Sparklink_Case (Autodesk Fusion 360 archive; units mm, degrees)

design "Sparklink Case" references "Halbrundschraube JIS B 1111 - M3x6 Stahl 4.6 Einfach", "SparkLink"
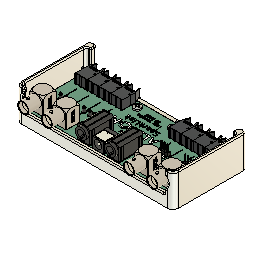
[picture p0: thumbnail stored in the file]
sketch "Skizze1" plane through (0, 0, 0) normal (0, 0, 1) x axis (1, 0, 0)
  line L1 (128, 0) -> (2, 0)
  line L2 (130, 53) -> (130, 2)
  line L3 (2, 55) -> (128, 55)
  line L4 (0, 2) -> (0, 53)
  line L5 (-0.1, 2) -> (-0.1, 53)
  line L6 (128, -0.1) -> (2, -0.1)
  line L7 (130.1, 53) -> (130.1, 2)
  line L8 (2, 55.1) -> (128, 55.1)
  line L9 (-3.1, 2) -> (-3.1, 53)
  line L10 (128, -3.1) -> (2, -3.1)
  line L11 (133.1, 53) -> (133.1, 2)
  line L12 (2, 58.1) -> (128, 58.1)
  arc A1 centre (2, 53) radius 2 clockwise from (0, 53) to (2, 55)
  arc A2 centre (2, 2) radius 2 clockwise from (2, 0) to (0, 2)
  arc A3 centre (128, 53) radius 2 clockwise from (128, 55) to (130, 53)
  arc A4 centre (128, 2) radius 2 clockwise from (130, 2) to (128, 0)
  arc A5 centre (2, 2) radius 2.1 clockwise from (2, -0.1) to (-0.1, 2)
  arc A6 centre (128, 2) radius 2.1 clockwise from (130.1, 2) to (128, -0.1)
  arc A7 centre (128, 53) radius 2.1 clockwise from (128, 55.1) to (130.1, 53)
  arc A8 centre (2, 53) radius 2.1 clockwise from (-0.1, 53) to (2, 55.1)
  arc A9 centre (2, 2) radius 5.1 clockwise from (2, -3.1) to (-3.1, 2)
  arc A10 centre (128, 2) radius 5.1 clockwise from (133.1, 2) to (128, -3.1)
  arc A11 centre (128, 53) radius 5.1 clockwise from (128, 58.1) to (133.1, 53)
  arc A12 centre (2, 53) radius 5.1 clockwise from (-3.1, 53) to (2, 58.1)
  point P1 (0, 0)
  point P2 (0, 0)
  point P4 (0, 55)
  point P3 (130, 0)
  horizontal L1
  vertical L2
  horizontal L3
  vertical L4
  coincident P1 P2
  coincident P4 L3
  coincident P4 L4
  tangent L3 A1
  tangent L4 A1
  coincident P2 L1
  coincident P2 L4
  tangent L1 A2
  tangent L4 A2
  equal A1 A2
  tangent L2 A3
  tangent L3 A3
  equal A1 A3
  coincident P3 L1
  coincident P3 L2
  tangent L1 A4
  tangent L2 A4
  equal A1 A4
  dimension "d1" distance P2 P3 = 130
  dimension "d2" distance P2 P4 = 55
  dimension "d3" radius A1 = 2
  dimension "d4" = 0.1
  dimension "d5" = 3.1
extrude "Extrusion1" new body sketch "Skizze1" profile of A8 L5 A7 A5 L7 L8 A6 L6 A12 L10 A9 A11 L11 L12 A10 L9 against normal blind 10
sketch "Skizze2" plane through (0, 0, -10) normal (0, 0, -1) x axis (1, 0, 0)
  line L1 (-0.1, -2) -> (-0.1, -53)
  line L2 (128, 0.1) -> (2, 0.1)
  line L3 (130.1, -53) -> (130.1, -2)
  line L4 (2, -55.1) -> (128, -55.1)
  line L5 (128, -58.1) -> (2, -58.1)
  line L6 (133.1, -2) -> (133.1, -53)
  line L7 (2, 3.1) -> (128, 3.1)
  line L8 (-3.1, -53) -> (-3.1, -2)
  arc A1 centre (2, -53) radius 2.1 clockwise from (2, -55.1) to (-0.1, -53)
  arc A2 centre (2, -2) radius 2.1 clockwise from (-0.1, -2) to (2, 0.1)
  arc A3 centre (128, -2) radius 2.1 clockwise from (128, 0.1) to (130.1, -2)
  arc A4 centre (128, -53) radius 2.1 clockwise from (130.1, -53) to (128, -55.1)
  arc A5 centre (2, -53) radius 5.1 clockwise from (2, -58.1) to (-3.1, -53)
  arc A6 centre (128, -53) radius 5.1 clockwise from (133.1, -53) to (128, -58.1)
  arc A7 centre (128, -2) radius 5.1 clockwise from (128, 3.1) to (133.1, -2)
  arc A8 centre (2, -2) radius 5.1 clockwise from (-3.1, -2) to (2, 3.1)
extrude "Extrusion2" add sketch "Skizze2" profile of A1 L1 A2 L2 A3 L3 A4 L4 against normal blind 3
extrude "Extrusion3" add of existing geometry blind 18
sketch "Skizze3" plane through (0, 0, -7) normal (0, 0, 1) x axis (-1, 0, 0)
  line L1 (-130.1, -53) -> (-130.1, -2)
  line L2 (-2, -55.1) -> (-128, -55.1)
  line L3 (0.1, -2) -> (0.1, -53)
  line L4 (-128, 0.1) -> (-2, 0.1)
  line L5 (-65, -55.1) -> (-65, 0.1)
  line L6 (-19.28, -8.18) -> (-110.72, -8.18)
  line L7 (-49.76, -49.455) -> (-80.24, -49.455)
  arc A1 centre (-128, -2) radius 2.1 clockwise from (-130.1, -2) to (-128, 0.1)
  arc A2 centre (-128, -53) radius 2.1 clockwise from (-128, -55.1) to (-130.1, -53)
  arc A3 centre (-2, -53) radius 2.1 clockwise from (0.1, -53) to (-2, -55.1)
  arc A4 centre (-2, -2) radius 2.1 clockwise from (-2, 0.1) to (0.1, -2)
  circle C1 centre (-110.72, -8.18) radius 1.45
  circle C2 centre (-19.28, -8.18) radius 1.45
  circle C3 centre (-80.24, -49.455) radius 1.45
  circle C4 centre (-49.76, -49.455) radius 1.45
  circle C5 centre (-110.72, -8.18) radius 4
  circle C6 centre (-19.28, -8.18) radius 4
  circle C7 centre (-49.76, -49.455) radius 4
  circle C8 centre (-80.24, -49.455) radius 4
  point P14 (-110.72, -8.18)
  point P15 (-19.28, -8.18)
  point P16 (-80.24, -49.455)
  point P17 (-49.76, -49.455)
  point P18 (-65, 0.1)
  point P19 (-65, -55.1)
  point P20 (-110.72, -8.18)
  point P21 (-19.28, -8.18)
  point P22 (-80.24, -49.455)
  point P23 (-49.76, -49.455)
  point P26 (-49.76, -49.455)
  horizontal P14 P15
  horizontal P16 P17
  midpoint L4 P18
  midpoint L2 P19
  coincident P14 P20
  coincident P15 P21
  coincident P16 P22
  coincident P17 P23
  concentric C1 C5
  concentric C2 C6
  coincident P23 P26
  concentric C3 C8
  dimension "d13" diameter C1 = 2.9
  dimension "d14" diameter C2 = 2.9
  dimension "d15" distance P14 P15 = 91.44
  dimension "d16" diameter C3 = 2.9
  dimension "d17" diameter C4 = 2.9
  dimension "d18" distance P16 P17 = 30.48
  dimension "d19" distance P14 P16 = 41.275
  dimension "d20" distance P16 L5 = 15.24 (= "d18 / 2")
  dimension "d21" distance P14 L5 = 45.72 (= "d15 / 2")
  dimension "d22" distance L4 L6 = 8.28
  dimension "d24" diameter C5 = 8
  dimension "d25" diameter C6 = 8
  dimension "d26" diameter C7 = 8
  dimension "d27" diameter C8 = 8
extrude "Extrusion4" add sketch "Skizze3" profile of C1 C2 C3 C4 C5 C6 C7 C8 along normal blind 5
component_insert "Komponente einfügen" sketch "Skizze3"
as_built_joint "Bestand"
joint "Zusammenfügen" alignAngle 180 alignOffsetX 0 alignOffsetY 0 alignOffsetZ 0
sketch "Skizze4" plane through (0, 58.1, 0) normal (0, 1, 0) x axis (-1, 0, 0)
  line L1 (-2, 18) -> (-2, -10)
  line L2 (-128, 18) -> (-2, 18)
  line L3 (-128, -10) -> (-128, 18)
  line L4 (-127.5, 18) -> (-128, 18)
  line L5 (-126.5, 0.56) -> (-126.5, 17)
  line L6 (-4.5, -0.44) -> (-125.5, -0.44)
  line L7 (-3.5, 17) -> (-3.5, 0.56)
  line L8 (-2.5, 18) -> (-2, 18)
  line L9 (-65, -18.88) -> (-65, 18)
  line L10 (-2, -10) -> (-128, -10)
  arc A1 centre (-2.5, 17) radius 1 clockwise from (-3.5, 17) to (-2.5, 18)
  arc A2 centre (-4.5, 0.56) radius 1 clockwise from (-3.5, 0.56) to (-4.5, -0.44)
  arc A3 centre (-125.5, 0.56) radius 1 clockwise from (-125.5, -0.44) to (-126.5, 0.56)
  arc A4 centre (-127.5, 17) radius 1 clockwise from (-127.5, 18) to (-126.5, 17)
  point P5 (-128, 18)
  point P6 (-128, 18)
  point P9 (-3.5, 18)
  point P4 (-2, 18)
  point P10 (-2, 18)
  point P8 (-3.5, -0.44)
  point P7 (-126.5, -0.44)
  point P23 (-65, 18)
  coincident P5 P6
  perpendicular L4 L5
  perpendicular L1 L6
  coincident L2 P9
  perpendicular L2 L7
  coincident P4 P10
  coincident P9 L7
  coincident P9 L8
  tangent L7 A1
  tangent L8 A1
  coincident P8 L6
  coincident P8 L7
  tangent L6 A2
  tangent L7 A2
  equal A1 A2
  coincident P7 L5
  coincident P7 L6
  tangent L5 A3
  tangent L6 A3
  equal A1 A3
  tangent L4 A4
  tangent L5 A4
  parallel L3 L5
  midpoint L2 P23
  midpoint L6 L9
  dimension "d34" distance P7 P8 = 123
  dimension "d35" distance P8 P9 = 18.44 (= "18 mm + 0.44 mm")
  dimension "d36" radius A1 = 1
  dimension "d37" radius A4 = 1
extrude "Extrusion5" cut sketch "Skizze4" profile of L2 L3 L5 L6 L7 A1 A2 A3 A4 against normal blind 5
sketch "Skizze5" plane through (0, -3.1, 0) normal (0, -1, 0) x axis (1, 0, 0)
  line L1 (128, 18) -> (128, -10)
  line L2 (2, 18) -> (128, 18)
  line L3 (2, -10) -> (2, 18)
  line L4 (2.5, 18) -> (2, 18)
  line L5 (4, 1.06) -> (4, 16.5)
  line L6 (124.5, -0.44) -> (5.5, -0.44)
  line L7 (126, 16.5) -> (126, 1.06)
  line L8 (127.5, 18) -> (128, 18)
  line L9 (128, -10) -> (2, -10)
  arc A1 centre (124.5, 1.06) radius 1.5 clockwise from (126, 1.06) to (124.5, -0.44)
  arc A2 centre (5.5, 1.06) radius 1.5 clockwise from (5.5, -0.44) to (4, 1.06)
  arc A3 centre (2.5, 16.5) radius 1.5 clockwise from (2.5, 18) to (4, 16.5)
  arc A4 centre (127.5, 16.5) radius 1.5 clockwise from (126, 16.5) to (127.5, 18)
  point P5 (2, 18)
  point P6 (2, 18)
  point P8 (126, -0.44)
  point P7 (4, -0.44)
  point P4 (128, 18)
  point P18 (128, 18)
  coincident P5 P6
  perpendicular L4 L5
  perpendicular L1 L6
  perpendicular L2 L7
  vertical L5
  coincident P8 L6
  coincident P8 L7
  tangent L6 A1
  tangent L7 A1
  coincident P7 L5
  coincident P7 L6
  tangent L5 A2
  tangent L6 A2
  tangent L4 A3
  tangent L5 A3
  equal A2 A3
  coincident P4 P18
  perpendicular L1 L8
  tangent L8 A4
  tangent L7 A4
  equal A1 A4
  equal L4 L8
  dimension "d40" distance L2 L6 = 18.44
  dimension "d41" distance P7 P8 = 122
  dimension "d45" radius A4 = 1.5
  dimension "d46" radius A3 = 1.5
extrude "Extrusion6" cut sketch "Skizze5" profile of L2 L5 L6 L7 A1 A2 A3 against normal blind 3
step "Schraube2"
step "Schraube4"
step "Schraube5"
step "Schraube6"
sketch "Skizze6" plane through (0, -3.1, 0) normal (0, -1, 0) x axis (1, 0, 0)
  line L1 (2, 18) -> (2.5, 18)
  line L2 (2, -10) -> (2, 18)
  line L3 (128, -10) -> (2, -10)
  line L4 (128, 18) -> (128, -10)
  line L5 (127.5, 18) -> (128, 18)
  line L6 (126, 1.06) -> (126, 16.5)
  line L7 (5.5, -0.44) -> (124.5, -0.44)
  line L8 (4, 16.5) -> (4, 1.06)
  arc A1 centre (2.5, 16.5) radius 1.5 clockwise from (2.5, 18) to (4, 16.5)
  arc A2 centre (127.5, 16.5) radius 1.5 clockwise from (126, 16.5) to (127.5, 18)
  arc A3 centre (124.5, 1.06) radius 1.5 clockwise from (126, 1.06) to (124.5, -0.44)
  arc A4 centre (5.5, 1.06) radius 1.5 clockwise from (5.5, -0.44) to (4, 1.06)
  circle C1 centre (9.12, 8.59) radius 7.5
  circle C2 centre (120.88, 8.59) radius 7.5
  point P18 (9.12, 8.59)
  point P19 (120.88, 8.59)
  dimension "d51" diameter C1 = 15
  dimension "d52" diameter C2 = 15
  dimension "d53" distance L8 P18 = 5.12
  dimension "d54" distance L7 P18 = 9.03
  dimension "d55" distance L6 P19 = 5.12 (= "d53")
  dimension "d56" distance L7 P19 = 9.03 (= "d54")
extrude "Extrusion7" cut sketch "Skizze6" profile of L2 L4 L6 L8 C1 C2 against normal blind 5
fillet "Abrundung1" radius 2
sketch "Skizze7" plane through (0, 0, 18) normal (0, 0, 1) x axis (-1, 0, 0)
  line L1 (-127.5, 3.1) -> (-127.5, 0.1)
  line L2 (-128, 3.1) -> (-127.5, 3.1)
  line L3 (-133.1, -53) -> (-133.1, -2)
  line L4 (-127.5, -58.1) -> (-128, -58.1)
  line L5 (-127.5, -55.1) -> (-127.5, -58.1)
  line L6 (-128, -55.1) -> (-127.5, -55.1)
  line L7 (-130.1, -2) -> (-130.1, -53)
  line L8 (-127.5, 0.1) -> (-128, 0.1)
  line L9 (-133.1, -56) -> (-133.1, -53)
  line L10 (-126.5, -61.0996) -> (-126.5, -58.0996)
  line L11 (-133.1, -61.0996) -> (-126.5, -61.0996)
  line L12 (-133.1, -56) -> (-133.1, -61.0996)
  line L13 (-126.5, -58.0996) -> (-127.5, -58.1)
  arc A1 centre (-128, -2) radius 5.1 clockwise from (-133.1, -2) to (-128, 3.1)
  arc A2 centre (-128, -53) radius 5.1 clockwise from (-128, -58.1) to (-133.1, -53)
  arc A3 centre (-128, -53) radius 2.1 clockwise from (-128, -55.1) to (-130.1, -53)
  arc A4 centre (-128, -2) radius 2.1 clockwise from (-130.1, -2) to (-128, 0.1)
  point P7 (-133.1, -53)
  point P16 (-133.1, -53)
  point P10 (-127.5, -58.1)
  point P21 (-127.5, -58.1)
  point P18 (-126.5, -58.0996)
  point P19 (-126.5, -61.0996)
  coincident P7 P16
  tangent A2 L9
  parallel L9 L10
  perpendicular L10 L11
  vertical L12
  coincident P10 P21
  dimension "d61" distance P18 P19 = 3
extrude "Extrusion8" add sketch "Skizze7" profile of A2 L4 L9 L10 L11 L12 L13 against normal blind 28
fillet "Abrundung4" radius 2.9
fillet "Abrundung5" radius 2.9
sketch "Skizze8" plane through (0, 0, 18) normal (0, 0, 1) x axis (-1, 0, 0)
  line L1 (-2.5, 0.1) -> (-2.5, 3.1)
  line L2 (-2, 0.1) -> (-2.5, 0.1)
  line L3 (0.1, -53) -> (0.1, -2)
  line L4 (-2.5, -55.1) -> (-2, -55.1)
  line L5 (-2.5, -58.1) -> (-2.5, -55.1)
  line L6 (-2, -58.1) -> (-2.5, -58.1)
  line L7 (3.1, -2) -> (3.1, -53)
  line L8 (-2.5, 3.1) -> (-2, 3.1)
  line L9 (3.1, -56) -> (3.1, -53)
  line L10 (-3.5, -61.1) -> (-3.5, -58.1)
  line L11 (3.1, -61.1) -> (-3.5, -61.1)
  line L12 (3.1, -56) -> (3.1, -61.1)
  line L13 (-2, -58.1) -> (-3.5, -58.1)
  arc A1 centre (-2, -2) radius 2.1 clockwise from (-2, 0.1) to (0.1, -2)
  arc A2 centre (-2, -53) radius 2.1 clockwise from (0.1, -53) to (-2, -55.1)
  arc A3 centre (-2, -53) radius 5.1 clockwise from (3.1, -53) to (-2, -58.1)
  arc A4 centre (-2, -2) radius 5.1 clockwise from (-2, 3.1) to (3.1, -2)
  point P13 (3.1, -53)
  point P16 (3.1, -53)
  point P12 (-2, -58.1)
  point P21 (-2, -58.1)
  point P18 (-3.5, -58.1)
  point P19 (-3.5, -61.1)
  coincident P13 P16
  tangent A3 L9
  vertical L10
  perpendicular L10 L11
  vertical L12
  coincident P12 P21
  tangent A3 L13
  dimension "d72" distance P18 P19 = 3
extrude "Extrusion9" add sketch "Skizze8" profile of L6 A3 L9 L10 L11 L12 L13 against normal blind 28
fillet "Abrundung6" radius 2.9
fillet "Abrundung7" radius 1
fillet "Abrundung9" radius 1
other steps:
joint_origin "Gelenkursprung"

design "Halbrundschraube JIS B 1111 - M3x6 Stahl 4.6 Einfach"
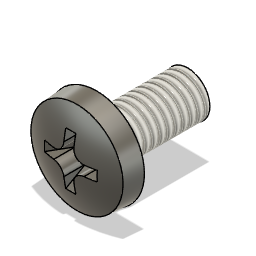
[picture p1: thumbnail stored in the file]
description: Halbrundschraube JIS B 1111 - M3x6
part number: BHS JIS B 1111 - M3x6 Stahl 4.6 Einfach
parameter "adsk_nomdia" = 3
parameter "adsk_nomlen" = 6
parameter "adsk_headdia" = 6.3
parameter "adsk_baseh" = 1.3
parameter "adsk_phildia" = 3.7
parameter "adsk_midfillet" = 0.1
parameter "adsk_thrlen" = 5.06
parameter "adsk_phildepth" = 1.53
parameter "adsk_thrrun" = 0.75
parameter "adsk_thrang" = 15
parameter "adsk_headang" = 5
parameter "adsk_ovalh" = 0.6
parameter "adsk_philwidth" = 0.662
sketch "Sketch1" plane through (0, 0, 0) normal (0, 1, 0) x axis (1, 0, 0)
  line L1 (0, 6) -> (0, -1.9)
  line L2 (-3.0363, -1.3) -> (-3.15, 0)
  line L3 (-1.299, 0) -> (-3.15, 0)
  line L4 (-1.5, 6) -> (0, 6)
  line L5 (-1.5, 0.94) -> (-1.5, 6)
  line L6 (-1.299, 0.19) -> (-1.5, 0.94)
  line L7 (-1.299, 0) -> (-1.299, 0.19)
  arc A1 centre (0, 6.0824) radius 7.9824 clockwise from (0, -1.9) to (-3.0363, -1.3)
  point P1 (0, 0)
  point P8 (0, -1.9)
  point P7 (0, 6.0824)
  point P2 (0, -1.9)
  point P6 (-1.299, 0)
  point P12 (-1.299, 0)
  point P10 (-1.5, 0.94)
  point P11 (-1.299, 0.19)
  point P5 (-3.0363, -1.3)
  vertical L1
  coincident P1 L1
  horizontal L3
  coincident P1 L3
  coincident L1 P8
  coincident L1 P7
  coincident P2 P8
  perpendicular L1 L4
  perpendicular L4 L5
  vertical L7
  coincident P6 P12
  dimension "d13" angle L1 L2 = 5 (= "adsk_headang")
  dimension "d14" = 6.3 (= "adsk_headdia")
  dimension "d18" = 3 (= "adsk_nomdia")
  dimension "d23" angle L5 L6 = 15 (= "adsk_thrang")
  dimension "d53" distance P2 L3 = 1.9 (= "adsk_baseh + adsk_ovalh")
  dimension "d55" distance L4 P10 = 5.06 (= "adsk_thrlen")
  dimension "d56" distance L3 L4 = 6 (= "adsk_nomlen")
  dimension "d57" distance L4 P11 = 5.81 (= "adsk_thrlen + adsk_thrrun")
  dimension "d60" distance P5 L3 = 1.3 (= "adsk_baseh")
revolve "Revolve1" sketch "Sketch1" AlongAngle 360
fillet "Fillet2" radius 0.1 (= "adsk_midfillet")
work_plane "WorkPlane1" AlongDistance 1.9 (= "adsk_baseh + adsk_ovalh")
sketch "Sketch2" plane through (0, 0, 1.9) normal (0, 0, 1) x axis (1, 0, 0)
  line L1 (1.85, 0) -> (-1.85, 0)
  line L2 (0, 1.85) -> (0, -1.85)
  line L3 (0.331, 1.85) -> (-0.331, 1.85)
  line L4 (0.331, 0.331) -> (0.331, 1.85)
  line L5 (1.85, 0.331) -> (0.331, 0.331)
  line L6 (1.85, -0.331) -> (1.85, 0.331)
  line L7 (0.331, -0.331) -> (1.85, -0.331)
  line L8 (0.331, -1.85) -> (0.331, -0.331)
  line L9 (-0.331, -1.85) -> (0.331, -1.85)
  line L10 (-0.331, -0.331) -> (-0.331, -1.85)
  line L11 (-1.85, -0.331) -> (-0.331, -0.331)
  line L12 (-1.85, 0.331) -> (-1.85, -0.331)
  line L13 (-0.331, 0.331) -> (-1.85, 0.331)
  line L14 (-0.331, 1.85) -> (-0.331, 0.331)
  point P1 (0, 0)
  point P17 (-0.331, 0.331)
  point P8 (0.331, 0.331)
  point P14 (-0.331, -0.331)
  point P3 (1.85, 0)
  point P4 (0, -1.85)
  point P5 (0, 1.85)
  point P2 (-1.85, 0)
  horizontal L1
  vertical L2
  midpoint L1 L2
  midpoint P1 L2
  perpendicular L2 L3
  perpendicular L3 L4
  perpendicular L4 L5
  perpendicular L1 L6
  perpendicular L6 L7
  perpendicular L1 L8
  perpendicular L8 L9
  perpendicular L9 L10
  perpendicular L8 L11
  perpendicular L11 L12
  perpendicular L12 L13
  vertical L14
  coincident L10 P17
  coincident P8 L8
  coincident L7 P14
  coincident L5 P17
  midpoint P3 L6
  midpoint P4 L9
  midpoint P5 L3
  midpoint P2 L12
  dimension "d58" distance L11 L13 = 0.662 (= "adsk_philwidth")
  dimension "d59" distance L4 L14 = 0.662 (= "adsk_philwidth")
  dimension "d61" distance L3 L9 = 3.7 (= "adsk_phildia")
  dimension "d62" distance L6 L12 = 3.7 (= "adsk_phildia")
extrude "Extrude1" new body sketch "Sketch2" profile of L3 L4 L5 L6 L7 L8 L9 L10 L11 L12 L13 L14 no distance stored
draft "Draft1" Angle1 -30 Angle2 0
fillet "Fillet1" radius 0.662 (= "adsk_philwidth")
combine "Combine1"
thread "Thread1" ThreadOffset 0 ThreadLength 10
joint_origin "JointOrigin1" OffsetX 0 OffsetY 0 OffsetZ 0 AngleZ 0

design "SparkLink"
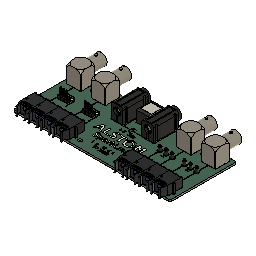
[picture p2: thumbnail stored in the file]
description: KiCad electronic assembly
part number: SparkLink 1
description: Part Number
part number: User Library-Test Point Keystone - 5001 BLACK_1
part number: User Library-Test Point Keystone - 5001 BLACK_2
part number: Test Point Keystone - 5001 BLACK
part number: PinHeader_1x03_P2.54mm_Vertical
part number: Broadcom_AFBR-16xxZ_Horizontal
part number: 571-0100
part number: 571-0100 PIN
part number: 51K201-400N5
base_feature "Base Feature1"
base_feature "Base Feature1"
base_feature "Base Feature1"
base_feature "Base Feature1"
base_feature "Base Feature1"
base_feature "Base Feature1"
base_feature "Base Feature1"
base_feature "Base Feature1"
base_feature "Base Feature1"
base_feature "Base Feature1"
base_feature "Base Feature1"
base_feature "Base Feature1"
base_feature "Base Feature1"
base_feature "Base Feature1"
base_feature "Base Feature1"
base_feature "Base Feature1"
base_feature "Base Feature1"
base_feature "Base Feature1"
base_feature "Base Feature1"
base_feature "Base Feature1"
base_feature "Base Feature1"
base_feature "Base Feature1"
base_feature "Base Feature1"
base_feature "Base Feature1"
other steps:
create_component "CreateComponent1"
create_component "CreateComponent1"
create_component "CreateComponent2"
create_component "CreateComponent2"
create_component "CreateComponent3"
create_component "CreateComponent4"
create_component "CreateComponent1"
create_component "CreateComponent2"
create_component "CreateComponent5"
create_component "CreateComponent6"
create_component "CreateComponent7"
create_component "CreateComponent8"
create_component "CreateComponent9"
create_component "CreateComponent10"
create_component "CreateComponent11"
create_component "CreateComponent12"
create_component "CreateComponent13"
create_component "CreateComponent14"
create_component "CreateComponent15"
create_component "CreateComponent1"
create_component "CreateComponent2"
create_component "CreateComponent16"
create_component "CreateComponent17"
create_component "CreateComponent18"
create_component "CreateComponent19"
create_component "CreateComponent20"
create_component "CreateComponent21"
